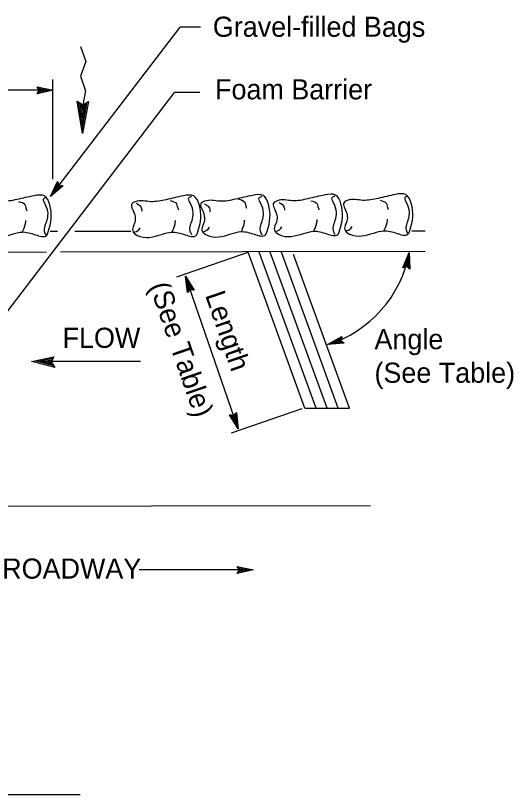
# Model space of a CAD drawing. Extents: x 6707406 to 6714471, y 1868570 to 1872341.
# Drawn here: x 6709921.3 to 6710099.4, y 1871429.7 to 1871708.3 of the extents above; entities that cross this region are included whole.
import ezdxf

# ---------------------------------------------------------------- set-up
doc = ezdxf.new("R2010")
doc.units = 0
for name, color, linetype in [('57 Undefined', 7, 'Continuous'), ('60 Nongeo Data', 7, 'Continuous'), ('63 Undefined', 7, 'Continuous')]:
    doc.layers.add(name, color=color, linetype=linetype)

msp = doc.modelspace()

# ---------------------------------------------------------------- linework, layer by layer
at = {"layer": '57 Undefined'}
for p, q in [((6709933.85, 1871643.55), (6709980.14, 1871704.21)), ((6709987.5, 1871704.21), (6709980.14, 1871704.21)), ((6709934.7, 1871649.82), (6709934.7, 1871685.42)), ((6709934.78, 1871681.58), (6709884.17, 1871681.58)), ((6709905.48, 1871585.64), (6709978.12, 1871680.81)), ((6709987.19, 1871680.81), (6709978.12, 1871680.81)), ((6710004.42, 1871623.57), (6709978.85, 1871614.76)), ((6710000.95, 1871560.49), (6709982.12, 1871615.15)), ((6710023.7, 1871567.6), (6709998.43, 1871558.89)), ((6710006.36, 1871510.02), (6709965.53, 1871510.02)), ((6709677.29, 1871429.73), (6709944.39, 1871429.73))]:
    msp.add_line(p, q, dxfattribs=at)
msp.add_arc((6710020.27, 1871631.22), 42.56, 287.3352, 349.5749, dxfattribs=at)
at = {"layer": '60 Nongeo Data'}
for p, q in [((6709929.02, 1871682.87), (6709929.02, 1871682.87)), ((6709934.78, 1871681.58), (6709934.78, 1871681.58)), ((6709929.02, 1871680.3), (6709929.02, 1871680.3)), ((6709936.33, 1871648.91), (6709936.33, 1871648.91)), ((6709938.36, 1871647.35), (6709938.36, 1871647.35)), ((6709933.85, 1871643.55), (6709933.85, 1871643.55)), ((6710024.8, 1871567.85), (6710004.48, 1871623.68)), ((6710028.79, 1871567.83), (6710008.46, 1871623.69)), ((6710032.77, 1871567.83), (6710012.44, 1871623.69)), ((6710036.76, 1871567.83), (6710016.42, 1871623.7)), ((6710040.73, 1871567.87), (6710020.73, 1871622.81)), ((6710062.12, 1871623.52), (6710062.12, 1871623.52)), ((6710059.82, 1871618.09), (6710059.82, 1871618.09)), ((6710062.34, 1871617.63), (6710062.34, 1871617.63)), ((6709982.12, 1871615.15), (6709982.12, 1871615.15)), ((6709982.78, 1871609.29), (6709982.78, 1871609.29)), ((6709985.2, 1871610.12), (6709985.2, 1871610.12)), ((6710038.07, 1871593.53), (6710038.07, 1871593.53)), ((6710032.95, 1871590.6), (6710032.95, 1871590.6)), ((6710038.83, 1871591.09), (6710038.83, 1871591.09)), ((6709927.04, 1871584.63), (6709934.97, 1871586.24)), ((6709934.97, 1871586.24), (6709934.09, 1871584.4)), ((6709934.97, 1871586.24), (6709934.97, 1871586.24)), ((6709935.39, 1871582.48), (6709927.04, 1871584.63)), ((6709927.04, 1871584.63), (6709927.04, 1871584.63)), ((6709966.02, 1871584.63), (6709928.77, 1871584.63)), ((6709935.04, 1871582.99), (6709928.91, 1871584.57)), ((6709928.92, 1871584.58), (6709934.71, 1871585.75)), ((6709930.79, 1871584.51), (6709934.52, 1871585.27)), ((6709934.66, 1871583.51), (6709930.79, 1871584.51)), ((6709932.66, 1871584.44), (6709934.26, 1871584.77)), ((6709934.37, 1871584), (6709932.66, 1871584.44)), ((6709934.09, 1871584.4), (6709935.39, 1871582.48)), ((6709935.39, 1871582.48), (6709935.39, 1871582.48)), ((6710000.29, 1871566.36), (6710000.29, 1871566.36)), ((6709997.87, 1871565.52), (6709997.87, 1871565.52)), ((6710000.95, 1871560.49), (6710000.95, 1871560.49)), ((6710000.6, 1871511.3), (6710000.6, 1871511.3)), ((6710000.6, 1871508.74), (6710000.6, 1871508.74)), ((6710006.36, 1871510.02), (6710006.36, 1871510.02))]:
    msp.add_line(p, q, dxfattribs=at)
for points in [[(6709929.02, 1871682.87), (6709934.78, 1871681.58), (6709929.02, 1871680.3), (6709929.22, 1871680.64), (6709933.44, 1871681.58), (6709929.22, 1871682.53), (6709929.43, 1871682.19), (6709932.13, 1871681.58), (6709929.43, 1871680.99), (6709929.63, 1871681.33), (6709930.8, 1871681.58), (6709929.63, 1871681.85), (6709929.79, 1871681.58), (6709929.02, 1871680.3), (6709929.79, 1871681.58)], [(6709938.36, 1871647.35), (6709933.85, 1871643.55), (6709936.33, 1871648.91), (6709936.47, 1871648.54), (6709934.65, 1871644.62), (6709937.97, 1871647.4), (6709937.58, 1871647.44), (6709935.46, 1871645.66), (6709936.62, 1871648.17), (6709936.77, 1871647.8), (6709936.26, 1871646.71), (6709937.18, 1871647.49), (6709936.88, 1871647.52), (6709936.33, 1871648.91), (6709936.88, 1871647.52)], [(6710059.82, 1871618.09), (6710062.12, 1871623.52), (6710062.34, 1871617.63), (6710062.04, 1871617.89), (6710061.89, 1871622.21), (6710060.19, 1871618.23), (6710060.56, 1871618.37), (6710061.64, 1871620.91), (6710061.74, 1871618.15), (6710061.45, 1871618.42), (6710061.4, 1871619.61), (6710060.93, 1871618.51), (6710061.22, 1871618.61), (6710062.34, 1871617.63), (6710061.22, 1871618.61)], [(6709982.78, 1871609.29), (6709982.12, 1871615.15), (6709985.2, 1871610.12), (6709984.81, 1871610.2), (6709982.56, 1871613.89), (6709983.04, 1871609.59), (6709983.29, 1871609.89), (6709982.98, 1871612.64), (6709984.43, 1871610.29), (6709984.04, 1871610.37), (6709983.41, 1871611.39), (6709983.55, 1871610.2), (6709983.75, 1871610.43), (6709985.2, 1871610.12), (6709983.75, 1871610.43)], [(6710038.83, 1871591.09), (6710032.95, 1871590.6), (6710038.07, 1871593.54), (6710037.97, 1871593.15), (6710034.22, 1871591), (6710038.54, 1871591.35), (6710038.24, 1871591.62), (6710035.48, 1871591.39), (6710037.88, 1871592.76), (6710037.79, 1871592.38), (6710036.75, 1871591.78), (6710037.95, 1871591.88), (6710037.72, 1871592.09), (6710038.07, 1871593.54), (6710037.72, 1871592.09)], [(6710000.29, 1871566.36), (6710000.95, 1871560.49), (6709997.87, 1871565.52), (6709998.26, 1871565.44), (6710000.52, 1871561.75), (6710000.04, 1871566.05), (6709999.78, 1871565.75), (6710000.09, 1871563), (6709998.65, 1871565.36), (6709999.04, 1871565.27), (6709999.66, 1871564.25), (6709999.53, 1871565.45), (6709999.33, 1871565.21), (6709997.87, 1871565.52), (6709999.33, 1871565.21)], [(6710000.6, 1871511.3), (6710006.36, 1871510.02), (6710000.6, 1871508.74), (6710000.8, 1871509.08), (6710005.02, 1871510.01), (6710000.8, 1871510.96), (6710001.01, 1871510.62), (6710003.71, 1871510.02), (6710001.01, 1871509.42), (6710001.21, 1871509.76), (6710002.38, 1871510.02), (6710001.21, 1871510.28), (6710001.37, 1871510.02), (6710000.6, 1871508.74), (6710001.37, 1871510.02)]]:
    msp.add_lwpolyline(points, close=True, dxfattribs=at)
for points in [[(6709933.67, 1871631.13), (6709936.36, 1871631.13)], [(6709942.48, 1871631.14), (6709962.52, 1871631.17)], [(6710063.01, 1871631.34), (6710067.78, 1871631.35)], [(6709678.2, 1871623.36), (6709932.4, 1871623.77)], [(6709937.44, 1871623.78), (6710067.78, 1871624)], [(6710024.8, 1871567.85), (6710040.73, 1871567.87)], [(6709578.14, 1871532.3), (6710048.25, 1871533.08)]]:
    msp.add_lwpolyline(points, dxfattribs=at)
for points in [[(6709910.11, 1871633.5), (6709909.69, 1871631.45), (6709911.34, 1871629.82), (6709920.08, 1871630.12), (6709923.67, 1871630.89), (6709928.44, 1871629.89), (6709932.39, 1871629.67), (6709933.02, 1871630.95), (6709933.57, 1871640.61), (6709931.65, 1871643.77), (6709928, 1871643.84), (6709921.75, 1871642.5), (6709916.26, 1871641.84), (6709910.72, 1871641.86), (6709909.33, 1871640.82), (6709909.83, 1871638.98), (6709910.51, 1871634.48), (6709910.03, 1871633.27)], [(6709963.61, 1871633.33), (6709963.22, 1871631.28), (6709964.87, 1871629.67), (6709973.62, 1871630.05), (6709977.19, 1871630.85), (6709981.97, 1871629.9), (6709985.92, 1871629.71), (6709986.54, 1871631), (6709987.01, 1871640.67), (6709985.06, 1871643.81), (6709981.41, 1871643.84), (6709975.17, 1871642.45), (6709969.69, 1871641.73), (6709964.14, 1871641.7), (6709962.77, 1871640.65), (6709963.28, 1871638.82), (6709964, 1871634.32), (6709963.54, 1871633.1)], [(6709988.38, 1871633.5), (6709987.99, 1871631.45), (6709989.64, 1871629.83), (6709998.39, 1871630.21), (6710001.96, 1871631.02), (6710006.74, 1871630.06), (6710010.69, 1871629.88), (6710011.31, 1871631.17), (6710011.78, 1871640.83), (6710009.83, 1871643.97), (6710006.18, 1871644), (6709999.94, 1871642.61), (6709994.46, 1871641.9), (6709988.91, 1871641.87), (6709987.54, 1871640.81), (6709988.05, 1871638.98), (6709988.77, 1871634.48), (6709988.31, 1871633.27)], [(6710014.3, 1871633.65), (6710013.9, 1871631.6), (6710015.56, 1871629.99), (6710024.3, 1871630.37), (6710027.88, 1871631.17), (6710032.66, 1871630.22), (6710036.61, 1871630.03), (6710037.23, 1871631.32), (6710037.69, 1871640.99), (6710035.74, 1871644.12), (6710032.09, 1871644.16), (6710025.85, 1871642.76), (6710020.37, 1871642.05), (6710014.83, 1871642.02), (6710013.45, 1871640.97), (6710013.97, 1871639.14), (6710014.69, 1871634.64), (6710014.22, 1871633.42)], [(6710039.45, 1871633.81), (6710039.05, 1871631.76), (6710040.71, 1871630.15), (6710049.45, 1871630.53), (6710053.03, 1871631.33), (6710057.81, 1871630.38), (6710061.76, 1871630.19), (6710062.38, 1871631.48), (6710062.84, 1871641.15), (6710060.89, 1871644.28), (6710057.25, 1871644.32), (6710051, 1871642.93), (6710045.53, 1871642.21), (6710039.98, 1871642.18), (6710038.6, 1871641.13), (6710039.12, 1871639.3), (6710039.84, 1871634.8), (6710039.37, 1871633.58)], [(6709922.42, 1871641.8), (6709924.68, 1871640.62), (6709924.97, 1871639.7), (6709925.33, 1871638.48)], [(6709932.38, 1871629.59), (6709931.73, 1871630.98), (6709932.64, 1871635.3), (6709932.85, 1871638.34), (6709931.54, 1871641.72), (6709931.33, 1871642.63), (6709932.33, 1871643.45)], [(6709976.61, 1871642.13), (6709978.88, 1871640.97), (6709979.18, 1871640.05), (6709979.55, 1871638.83)], [(6709984.4, 1871629.84), (6709983.73, 1871631.22), (6709984.6, 1871635.55), (6709984.78, 1871638.59), (6709983.44, 1871641.95), (6709983.22, 1871642.87), (6709984.22, 1871643.7)], [(6710001.01, 1871642.68), (6710003.28, 1871641.52), (6710003.57, 1871640.6), (6710003.94, 1871639.38)], [(6710009.55, 1871629.81), (6710008.88, 1871631.19), (6710009.75, 1871635.52), (6710009.93, 1871638.56), (6710008.59, 1871641.92), (6710008.37, 1871642.84), (6710009.37, 1871643.67)], [(6710026.91, 1871642.07), (6710029.18, 1871640.91), (6710029.48, 1871639.99), (6710029.85, 1871638.77)], [(6710035.65, 1871629.96), (6710034.98, 1871631.34), (6710035.86, 1871635.67), (6710036.03, 1871638.72), (6710034.7, 1871642.08), (6710034.48, 1871642.99), (6710035.47, 1871643.82)], [(6710051.68, 1871642.23), (6710053.95, 1871641.07), (6710054.25, 1871640.16), (6710054.62, 1871638.93)], [(6710061.76, 1871630.12), (6710061.09, 1871631.49), (6710061.96, 1871635.82), (6710062.14, 1871638.87), (6710060.8, 1871642.23), (6710060.58, 1871643.15), (6710061.57, 1871643.98)], [(6709964.45, 1871641.17), (6709966.11, 1871639.94), (6709966.47, 1871638.33)], [(6709988.83, 1871640.96), (6709990.49, 1871639.72), (6709990.86, 1871638.12)], [(6710015.51, 1871641.48), (6710017.17, 1871640.25), (6710017.54, 1871638.65)], [(6709923.67, 1871630.82), (6709924.86, 1871633.84), (6709925.04, 1871635.06)], [(6709977.19, 1871630.78), (6709978.36, 1871633.81), (6709978.52, 1871635.03)], [(6710001.96, 1871630.94), (6710003.13, 1871633.98), (6710003.29, 1871635.2)], [(6710027.88, 1871631.1), (6710029.04, 1871634.13), (6710029.21, 1871635.35)], [(6710053.03, 1871631.26), (6710054.2, 1871634.29), (6710054.36, 1871635.51)], [(6709963.44, 1871630.75), (6709965.42, 1871631.72), (6709965.89, 1871632.4)], [(6709988.21, 1871630.91), (6709990.19, 1871631.88), (6709990.66, 1871632.56)], [(6710014.12, 1871631.06), (6710016.11, 1871632.04), (6710016.57, 1871632.72)], [(6710039.28, 1871631.23), (6710041.26, 1871632.2), (6710041.72, 1871632.88)]]:
    msp.add_spline(points, degree=3, dxfattribs=at)
at = {"layer": '63 Undefined'}
for p, q in [((6709945.26, 1871666.07), (6709943.33, 1871677.63)), ((6709943.33, 1871677.63), (6709945.36, 1871676.43)), ((6709945.29, 1871668.83), (6709943.87, 1871677.31)), ((6709945.31, 1871671.57), (6709944.41, 1871676.99)), ((6709945.34, 1871674.37), (6709944.96, 1871676.67)), ((6709947.4, 1871677.59), (6709945.26, 1871666.07)), ((6709946.86, 1871677.28), (6709945.29, 1871668.83)), ((6709946.31, 1871676.97), (6709945.31, 1871671.57)), ((6709945.76, 1871676.66), (6709945.34, 1871674.37)), ((6709945.36, 1871676.43), (6709947.4, 1871677.59))]:
    msp.add_line(p, q, dxfattribs=at)
msp.add_lwpolyline([(6709944.59, 1871697.21), (6709946.45, 1871691.91), (6709944.5, 1871686.64), (6709946.35, 1871681.34), (6709945.36, 1871676.43), (6709945.26, 1871666.07)], dxfattribs=at)

# ---------------------------------------------------------------- texts
at = {"layer": '57 Undefined'}
for s, height, p in [('Gravel-filled Bags', 7.1998, (6709991.89, 1871700.71)), ('Foam Barrier', 7.1998, (6709992.67, 1871678.32)), ('Angle ', 7.2, (6710049.69, 1871588.96)), ('(See Table)', 7.1998, (6710049.69, 1871576.96)), ('ROADWAY', 7.2, (6709916.54, 1871506.91))]:
    msp.add_text(s, height=height, dxfattribs=at).set_placement(p)
for s, height, p in [('(See Table)', 7.1998, (6709969.12, 1871611.6)), ('Length', 7.2, (6709989.05, 1871608.34))]:
    msp.add_text(s, height=height, rotation=289.0018, dxfattribs=at).set_placement(p)
at = {"layer": '60 Nongeo Data'}
msp.add_text('FLOW', height=7.2, dxfattribs=at).set_placement((6709938.13, 1871589.45))

doc.saveas('drawing.dxf')
